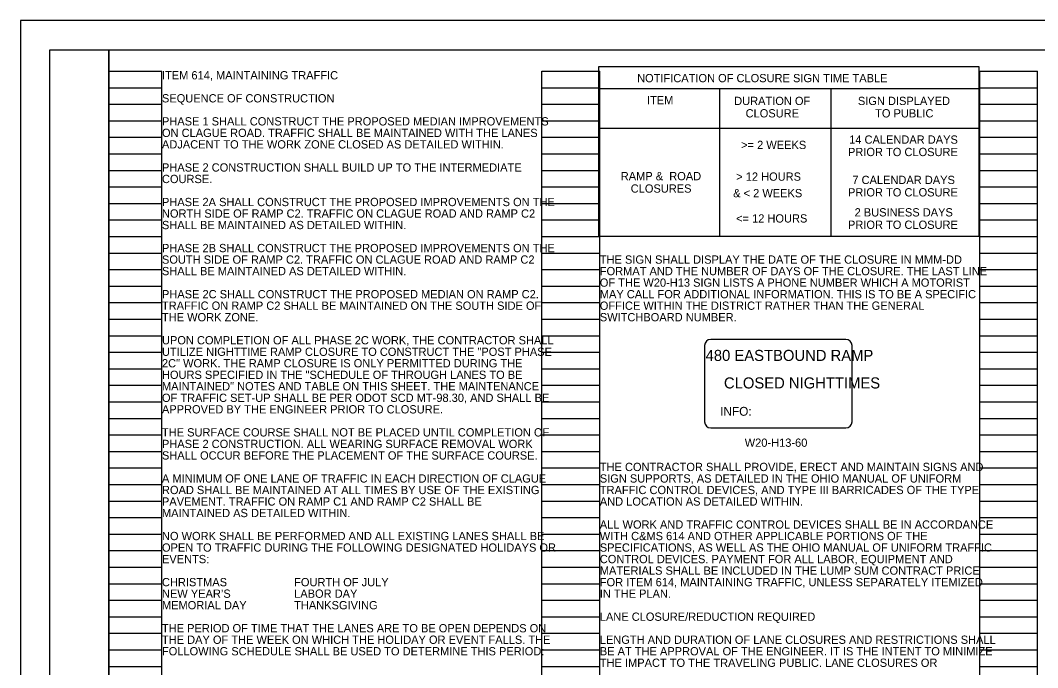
# Model space of a CAD drawing. Extents: x 0 to 34, y 0 to 22.
# Drawn here: x 0 to 17.24, y 11.04 to 22 of the extents above; entities that cross this region are included whole.
import ezdxf

# ---------------------------------------------------------------- set-up
doc = ezdxf.new("R2010")
doc.units = 0
for name, color, linetype in [('SH_Border', 7, 'Continuous'), ('SH_Cut_Line', 7, 'Continuous'), ('SH_Data', 7, 'Continuous'), ('SH_Text', 7, 'Continuous'), ('SN_P_Signs', 7, 'Continuous'), ('SN_P_Text', 7, 'Continuous')]:
    doc.layers.add(name, color=color, linetype=linetype)

msp = doc.modelspace()

# ---------------------------------------------------------------- linework, layer by layer
at = {"layer": 'SH_Border'}
for points in [[(0.5, 21.5), (1.5, 21.5), (1.5, 0.5), (0.5, 0.5)], [(1.5, 21.5), (33.5, 21.5), (33.5, 0.5), (1.5, 0.5)]]:
    msp.add_lwpolyline(points, close=True, dxfattribs=at)
at = {"layer": 'SH_Cut_Line'}
msp.add_lwpolyline([(0, 0), (34, 0), (34, 22), (0, 22)], close=True, dxfattribs=at)
at = {"layer": 'SH_Data'}
for p, q in [((1.5, 0.98), (1.5, 21.14)), ((1.5, 21.14), (2.4, 21.14)), ((2.4, 0.98), (2.4, 21.14)), ((8.84, 0.98), (8.84, 21.14)), ((8.84, 21.14), (9.82, 21.14)), ((9.82, 0.98), (9.82, 21.14)), ((16.26, 0.98), (16.26, 21.14)), ((16.26, 21.14), (17.24, 21.14)), ((17.24, 0.98), (17.24, 21.14)), ((1.5, 20.86), (2.4, 20.86)), ((8.84, 20.86), (9.82, 20.86)), ((16.26, 20.86), (17.24, 20.86)), ((1.5, 20.58), (2.4, 20.58)), ((8.84, 20.58), (9.82, 20.58)), ((16.26, 20.58), (17.24, 20.58)), ((1.5, 20.3), (2.4, 20.3)), ((8.84, 20.3), (9.82, 20.3)), ((16.26, 20.3), (17.24, 20.3)), ((1.5, 20.02), (2.4, 20.02)), ((8.84, 20.02), (9.82, 20.02)), ((16.26, 20.02), (17.24, 20.02)), ((1.5, 19.74), (2.4, 19.74)), ((8.84, 19.74), (9.82, 19.74)), ((16.26, 19.74), (17.24, 19.74)), ((1.5, 19.46), (2.4, 19.46)), ((8.84, 19.46), (9.82, 19.46)), ((16.26, 19.46), (17.24, 19.46)), ((1.5, 19.18), (2.4, 19.18)), ((8.84, 19.18), (9.82, 19.18)), ((16.26, 19.18), (17.24, 19.18)), ((1.5, 18.9), (2.4, 18.9)), ((8.84, 18.9), (9.82, 18.9)), ((16.26, 18.9), (17.24, 18.9)), ((1.5, 18.62), (2.4, 18.62)), ((8.84, 18.62), (9.82, 18.62)), ((16.26, 18.62), (17.24, 18.62)), ((1.5, 18.34), (2.4, 18.34)), ((8.84, 18.34), (9.82, 18.34)), ((16.26, 18.34), (17.24, 18.34)), ((1.5, 18.06), (2.4, 18.06)), ((8.84, 18.06), (9.82, 18.06)), ((16.26, 18.06), (17.24, 18.06)), ((1.5, 17.78), (2.4, 17.78)), ((8.84, 17.78), (9.82, 17.78)), ((16.26, 17.78), (17.24, 17.78)), ((1.5, 17.5), (2.4, 17.5)), ((8.84, 17.5), (9.82, 17.5)), ((16.26, 17.5), (17.24, 17.5)), ((1.5, 17.22), (2.4, 17.22)), ((8.84, 17.22), (9.82, 17.22)), ((16.26, 17.22), (17.24, 17.22)), ((1.5, 16.94), (2.4, 16.94)), ((8.84, 16.94), (9.82, 16.94)), ((16.26, 16.94), (17.24, 16.94)), ((1.5, 16.66), (2.4, 16.66)), ((8.84, 16.66), (9.82, 16.66)), ((16.26, 16.66), (17.24, 16.66)), ((1.5, 16.38), (2.4, 16.38)), ((8.84, 16.38), (9.82, 16.38)), ((16.26, 16.38), (17.24, 16.38)), ((1.5, 16.1), (2.4, 16.1)), ((8.84, 16.1), (9.82, 16.1)), ((16.26, 16.1), (17.24, 16.1)), ((1.5, 15.82), (2.4, 15.82)), ((8.84, 15.82), (9.82, 15.82)), ((16.26, 15.82), (17.24, 15.82)), ((1.5, 15.54), (2.4, 15.54)), ((8.84, 15.54), (9.82, 15.54)), ((16.26, 15.54), (17.24, 15.54)), ((1.5, 15.26), (2.4, 15.26)), ((8.84, 15.26), (9.82, 15.26)), ((16.26, 15.26), (17.24, 15.26)), ((1.5, 14.98), (2.4, 14.98)), ((8.84, 14.98), (9.82, 14.98)), ((16.26, 14.98), (17.24, 14.98)), ((1.5, 14.7), (2.4, 14.7)), ((8.84, 14.7), (9.82, 14.7)), ((16.26, 14.7), (17.24, 14.7)), ((1.5, 14.42), (2.4, 14.42)), ((8.84, 14.42), (9.82, 14.42)), ((16.26, 14.42), (17.24, 14.42)), ((1.5, 14.14), (2.4, 14.14)), ((8.84, 14.14), (9.82, 14.14)), ((16.26, 14.14), (17.24, 14.14)), ((1.5, 13.86), (2.4, 13.86)), ((8.84, 13.86), (9.82, 13.86)), ((16.26, 13.86), (17.24, 13.86)), ((1.5, 13.58), (2.4, 13.58)), ((8.84, 13.58), (9.82, 13.58)), ((16.26, 13.58), (17.24, 13.58)), ((1.5, 13.3), (2.4, 13.3)), ((8.84, 13.3), (9.82, 13.3)), ((16.26, 13.3), (17.24, 13.3)), ((1.5, 13.02), (2.4, 13.02)), ((8.84, 13.02), (9.82, 13.02)), ((16.26, 13.02), (17.24, 13.02)), ((1.5, 12.74), (2.4, 12.74)), ((8.84, 12.74), (9.82, 12.74)), ((16.26, 12.74), (17.24, 12.74)), ((1.5, 12.46), (2.4, 12.46)), ((8.84, 12.46), (9.82, 12.46)), ((16.26, 12.46), (17.24, 12.46)), ((1.5, 12.18), (2.4, 12.18)), ((8.84, 12.18), (9.82, 12.18)), ((16.26, 12.18), (17.24, 12.18)), ((1.5, 11.9), (2.4, 11.9)), ((8.84, 11.9), (9.82, 11.9)), ((16.26, 11.9), (17.24, 11.9)), ((1.5, 11.62), (2.4, 11.62)), ((8.84, 11.62), (9.82, 11.62)), ((16.26, 11.62), (17.24, 11.62)), ((1.5, 11.34), (2.4, 11.34)), ((8.84, 11.34), (9.82, 11.34)), ((16.26, 11.34), (17.24, 11.34)), ((1.5, 11.06), (2.4, 11.06)), ((8.84, 11.06), (9.82, 11.06)), ((16.26, 11.06), (17.24, 11.06))]:
    msp.add_line(p, q, dxfattribs=at)
at = {"layer": 'SH_Text'}
for p, q in [((9.801, 20.845), (16.241, 20.845)), ((11.85, 20.845), (11.85, 18.346)), ((13.735, 20.845), (13.735, 18.346)), ((9.801, 20.173), (16.241, 20.173)), ((9.801, 18.346), (16.241, 18.346))]:
    msp.add_line(p, q, dxfattribs=at)
msp.add_lwpolyline([(9.801, 18.346), (9.801, 21.22), (16.241, 21.22), (16.241, 18.346)], dxfattribs=at)
at = {"layer": 'SN_P_Signs'}
for p, q in [((13.991, 16.598), (11.699, 16.598)), ((11.595, 16.494), (11.595, 15.202)), ((14.095, 15.202), (14.095, 16.494)), ((11.699, 15.098), (13.991, 15.098))]:
    msp.add_line(p, q, dxfattribs=at)
for centre, start, end in [((11.699, 16.494), 90, 180), ((13.991, 16.494), 0, 90), ((11.699, 15.202), 180, 270), ((13.991, 15.202), 270, 360)]:
    msp.add_arc(centre, 0.104, start, end, dxfattribs=at)

# ---------------------------------------------------------------- texts
at = {"layer": 'SH_Text'}
for s, p in [('ITEM 614, MAINTAINING TRAFFIC', (2.4, 21)), (' NOTIFICATION OF CLOSURE SIGN TIME TABLE', (10.4, 20.952)), ('SEQUENCE OF CONSTRUCTION', (2.4, 20.61)), ('ITEM          ', (10.619, 20.578)), ('DURATION OF ', (12.097, 20.566)), ('SIGN DISPLAYED', (14.194, 20.566)), ('PHASE 1 SHALL CONSTRUCT THE PROPOSED MEDIAN IMPROVEMENTS ', (2.4, 20.22)), ('CLOSURE', (12.291, 20.356)), ('TO PUBLIC', (14.486, 20.356)), ('ON CLAGUE ROAD. TRAFFIC SHALL BE MAINTAINED WITH THE LANES ', (2.4, 20.025)), ('14 CALENDAR DAYS ', (14.046, 19.911)), ('ADJACENT TO THE WORK ZONE CLOSED AS DETAILED WITHIN.', (2.4, 19.83)), ('>= 2 WEEKS', (12.215, 19.821)), ('PRIOR TO CLOSURE', (14.026, 19.701)), ('PHASE 2 CONSTRUCTION SHALL BUILD UP TO THE INTERMEDIATE ', (2.4, 19.439)), ('COURSE.', (2.4, 19.244)), ('RAMP &  ROAD', (10.175, 19.292)), ('                > 12 HOURS      ', (11.3, 19.284)), ('7 CALENDAR DAYS ', (14.1, 19.228)), ('CLOSURES', (10.344, 19.082)), ('               & < 2 WEEKS      ', (11.3, 19.004)), ('PRIOR TO CLOSURE', (14.026, 19.018)), ('PHASE 2A SHALL CONSTRUCT THE PROPOSED IMPROVEMENTS ON THE ', (2.4, 18.854)), ('NORTH SIDE OF RAMP C2. TRAFFIC ON CLAGUE ROAD AND RAMP C2 ', (2.4, 18.659)), ('2 BUSINESS DAYS ', (14.138, 18.679)), ('               <= 12 HOURS       ', (11.35, 18.576)), ('SHALL BE MAINTAINED AS DETAILED WITHIN.', (2.4, 18.464)), ('PRIOR TO CLOSURE', (14.026, 18.469)), ('PHASE 2B SHALL CONSTRUCT THE PROPOSED IMPROVEMENTS ON THE ', (2.4, 18.074)), ('SOUTH SIDE OF RAMP C2. TRAFFIC ON CLAGUE ROAD AND RAMP C2 ', (2.4, 17.879)), ('THE SIGN SHALL DISPLAY THE DATE OF THE CLOSURE IN MMM-DD ', (9.82, 17.879)), ('SHALL BE MAINTAINED AS DETAILED WITHIN.', (2.4, 17.684)), ('FORMAT AND THE NUMBER OF DAYS OF THE CLOSURE. THE LAST LINE ', (9.82, 17.684)), ('OF THE W20-H13 SIGN LISTS A PHONE NUMBER WHICH A MOTORIST ', (9.82, 17.489)), ('PHASE 2C SHALL CONSTRUCT THE PROPOSED MEDIAN ON RAMP C2. ', (2.4, 17.293)), ('MAY CALL FOR ADDITIONAL INFORMATION. THIS IS TO BE A SPECIFIC ', (9.82, 17.293)), ('TRAFFIC ON RAMP C2 SHALL BE MAINTAINED ON THE SOUTH SIDE OF ', (2.4, 17.098)), ('OFFICE WITHIN THE DISTRICT RATHER THAN THE GENERAL ', (9.82, 17.098)), ('THE WORK ZONE. ', (2.4, 16.903)), ('SWITCHBOARD NUMBER. ', (9.82, 16.903)), ('UPON COMPLETION OF ALL PHASE 2C WORK, THE CONTRACTOR SHALL ', (2.4, 16.513)), ('UTILIZE NIGHTTIME RAMP CLOSURE TO CONSTRUCT THE "POST PHASE ', (2.4, 16.318)), ('2C" WORK. THE RAMP CLOSURE IS ONLY PERMITTED DURING THE ', (2.4, 16.123)), ('HOURS SPECIFIED IN THE "SCHEDULE OF THROUGH LANES TO BE ', (2.4, 15.928)), ('MAINTAINED" NOTES AND TABLE ON THIS SHEET. THE MAINTENANCE ', (2.4, 15.733)), ('OF TRAFFIC SET-UP SHALL BE PER ODOT SCD MT-98.30, AND SHALL BE ', (2.4, 15.538)), ('APPROVED BY THE ENGINEER PRIOR TO CLOSURE.', (2.4, 15.343)), ('THE SURFACE COURSE SHALL NOT BE PLACED UNTIL COMPLETION OF ', (2.4, 14.953)), ('PHASE 2 CONSTRUCTION. ALL WEARING SURFACE REMOVAL WORK  ', (2.4, 14.757)), ('SHALL OCCUR BEFORE THE PLACEMENT OF THE SURFACE COURSE.', (2.4, 14.562)), ('THE CONTRACTOR SHALL PROVIDE, ERECT AND MAINTAIN SIGNS AND ', (9.82, 14.367)), ('A MINIMUM OF ONE LANE OF TRAFFIC IN EACH DIRECTION OF CLAGUE ', (2.4, 14.172)), ('SIGN SUPPORTS, AS DETAILED IN THE OHIO MANUAL OF UNIFORM ', (9.82, 14.172)), ('ROAD SHALL BE MAINTAINED AT ALL TIMES BY USE OF THE EXISTING ', (2.4, 13.977)), ('TRAFFIC CONTROL DEVICES, AND TYPE III BARRICADES OF THE TYPE ', (9.82, 13.977)), ('PAVEMENT. TRAFFIC ON RAMP C1 AND RAMP C2 SHALL BE ', (2.4, 13.782)), ('AND LOCATION AS DETAILED WITHIN.', (9.82, 13.782)), ('MAINTAINED AS DETAILED WITHIN.', (2.4, 13.587)), ('ALL WORK AND TRAFFIC CONTROL DEVICES SHALL BE IN ACCORDANCE ', (9.82, 13.392)), ('NO WORK SHALL BE PERFORMED AND ALL EXISTING LANES SHALL BE ', (2.4, 13.197)), ('WITH C&MS 614 AND OTHER APPLICABLE PORTIONS OF THE ', (9.82, 13.197)), ('OPEN TO TRAFFIC DURING THE FOLLOWING DESIGNATED HOLIDAYS OR ', (2.4, 13.002)), ('SPECIFICATIONS, AS WELL AS THE OHIO MANUAL OF UNIFORM TRAFFIC ', (9.82, 13.002)), ('EVENTS: ', (2.4, 12.807)), ('CONTROL DEVICES. PAYMENT FOR ALL LABOR, EQUIPMENT AND ', (9.82, 12.807)), ('MATERIALS SHALL BE INCLUDED IN THE LUMP SUM CONTRACT PRICE ', (9.82, 12.612)), ('CHRISTMAS ', (2.4, 12.416)), ('FOURTH OF JULY', (4.64, 12.416)), ('FOR ITEM 614, MAINTAINING TRAFFIC, UNLESS SEPARATELY ITEMIZED ', (9.82, 12.416)), ('NEW YEAR’S ', (2.4, 12.221)), ('LABOR DAY', (4.64, 12.221)), ('IN THE PLAN.', (9.82, 12.221)), ('MEMORIAL DAY ', (2.4, 12.026)), ('THANKSGIVING', (4.64, 12.026)), ('LANE CLOSURE/REDUCTION REQUIRED', (9.82, 11.831)), ('THE PERIOD OF TIME THAT THE LANES ARE TO BE OPEN DEPENDS ON ', (2.4, 11.636)), ('THE DAY OF THE WEEK ON WHICH THE HOLIDAY OR EVENT FALLS. THE ', (2.4, 11.441)), ('LENGTH AND DURATION OF LANE CLOSURES AND RESTRICTIONS SHALL ', (9.82, 11.441)), ('FOLLOWING SCHEDULE SHALL BE USED TO DETERMINE THIS PERIOD:', (2.4, 11.246)), ('BE AT THE APPROVAL OF THE ENGINEER. IT IS THE INTENT TO MINIMIZE ', (9.82, 11.246)), ('THE IMPACT TO THE TRAVELING PUBLIC. LANE CLOSURES OR ', (9.82, 11.051))]:
    msp.add_text(s, height=0.14, dxfattribs=at).set_placement(p)
at = {"layer": 'SN_P_Signs'}
for s, height, p in [('480 EASTBOUND RAMP', 0.1875, (11.613, 16.232)), ('CLOSED NIGHTTIMES', 0.1875, (11.924, 15.766)), ('INFO:', 0.1499, (11.859, 15.304))]:
    msp.add_text(s, height=height, dxfattribs=at).set_placement(p)
at = {"layer": 'SN_P_Text'}
msp.add_text('W20-H13-60', height=0.14, dxfattribs=at).set_placement((12.276, 14.778))

doc.saveas('drawing.dxf')
